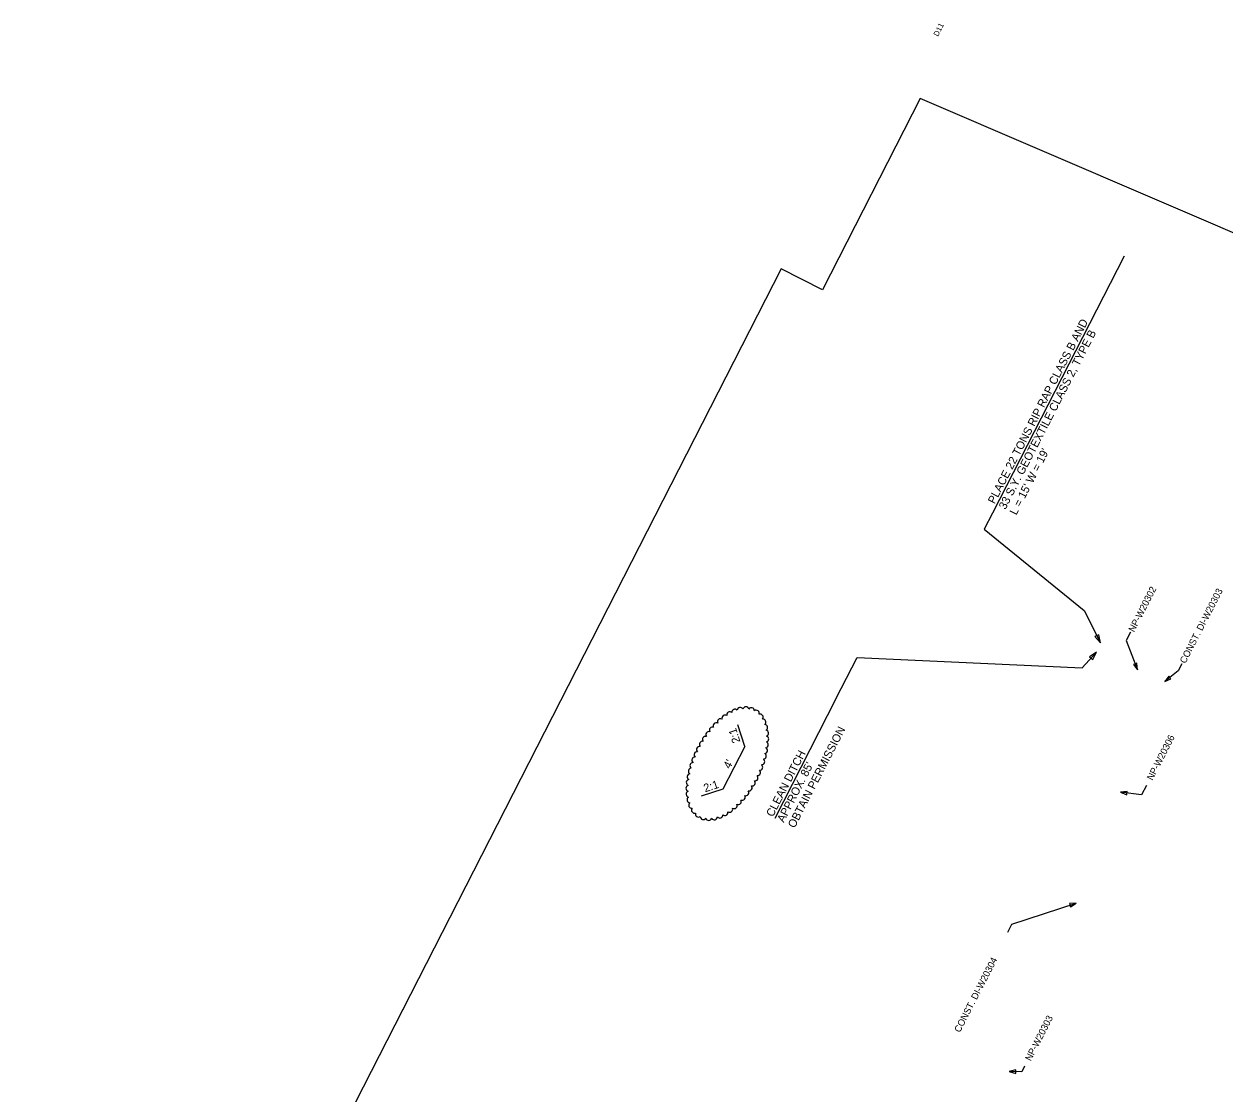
# Model space of a CAD drawing. Extents: x 1614575 to 1616117, y 1096819 to 1098677.
# Drawn here: x 1614575 to 1615461, y 1097888 to 1098677 of the extents above; entities that cross this region are included whole.
import ezdxf

# ---------------------------------------------------------------- set-up
doc = ezdxf.new("R2010")
doc.units = 0
for name, color, linetype in [('Level 19', 7, 'Continuous'), ('Level 2', 7, 'Continuous'), ('Level 20', 7, 'Continuous'), ('Level 8', 7, 'Continuous')]:
    doc.layers.add(name, color=color, linetype=linetype)

msp = doc.modelspace()

# ---------------------------------------------------------------- linework, layer by layer
at = {"layer": 'Level 19'}
msp.add_lwpolyline([(1614788.78, 1097308.44), (1614938.71, 1097183.17), (1614915.33, 1097153.87), (1614985.17, 1097098.15), (1614971.19, 1097080.18), (1615113.55, 1096967.95), (1615306.49, 1096819.15), (1616070.13, 1098243.47), (1615778.49, 1098389.73), (1615502.74, 1098507.9), (1615236.09, 1098622.18), (1615164.05, 1098481.19), (1615133.61, 1098496.74), (1614575.12, 1097403.7), (1614683.85, 1097348.14)], close=True, dxfattribs=at)
msp.add_lwpolyline([(1614788.78, 1097308.44), (1614938.71, 1097183.17), (1614915.33, 1097153.87), (1614985.17, 1097098.15), (1614971.19, 1097080.18), (1615113.55, 1096967.95), (1615306.49, 1096819.15), (1616070.13, 1098243.47), (1615778.49, 1098389.73), (1615502.74, 1098507.9), (1615236.09, 1098622.18), (1615164.05, 1098481.19), (1615133.61, 1098496.74), (1614575.12, 1097403.7), (1614683.85, 1097348.14)], close=True, dxfattribs=at)
msp.add_lwpolyline([(1614788.78, 1097308.44), (1614938.71, 1097183.17), (1614915.33, 1097153.87), (1614985.17, 1097098.15), (1614971.19, 1097080.18), (1615113.55, 1096967.95), (1615306.49, 1096819.15), (1616070.13, 1098243.47), (1615778.49, 1098389.73), (1615502.74, 1098507.9), (1615236.09, 1098622.18), (1615164.05, 1098481.19), (1615133.61, 1098496.74), (1614575.12, 1097403.7), (1614683.85, 1097348.14)], close=True, dxfattribs=at)
msp.add_lwpolyline([(1614788.78, 1097308.44), (1614938.71, 1097183.17), (1614915.33, 1097153.87), (1614985.17, 1097098.15), (1614971.19, 1097080.18), (1615113.55, 1096967.95), (1615306.49, 1096819.15), (1616070.13, 1098243.47), (1615778.49, 1098389.73), (1615502.74, 1098507.9), (1615236.09, 1098622.18), (1615164.05, 1098481.19), (1615133.61, 1098496.74), (1614575.12, 1097403.7), (1614683.85, 1097348.14)], close=True, dxfattribs=at)
msp.add_lwpolyline([(1614788.78, 1097308.44), (1614938.71, 1097183.17), (1614915.33, 1097153.87), (1614985.17, 1097098.15), (1614971.19, 1097080.18), (1615113.55, 1096967.95), (1615306.49, 1096819.15), (1616070.13, 1098243.47), (1615778.49, 1098389.73), (1615502.74, 1098507.9), (1615236.09, 1098622.18), (1615164.05, 1098481.19), (1615133.61, 1098496.74), (1614575.12, 1097403.7), (1614683.85, 1097348.14)], close=True, dxfattribs=at)
at = {"layer": 'Level 2'}
for p, q in [((1615106.71, 1098144.45), (1615101.61, 1098160.27)), ((1615106.71, 1098144.45), (1615090.51, 1098112.82)), ((1615090.51, 1098112.82), (1615074.69, 1098107.72))]:
    msp.add_line(p, q, dxfattribs=at)
for centre, start, end in [((1615095.69, 1098167.7), 48.24258, 193.24258), ((1615099.46, 1098169.61), 40.62705, 185.62705), ((1615103.45, 1098170.92), 30.63786, 175.63786), ((1615107.56, 1098171.38), 17.23139, 162.23139), ((1615111.58, 1098170.75), 359.95632, 144.95632), ((1615115.18, 1098168.91), 340.77376, 125.77376), ((1615118.04, 1098166.01), 323.49869, 108.49869), ((1615085.78, 1098159.67), 63.6026, 208.6026), ((1615088.86, 1098162.63), 59.29942, 204.29942), ((1615092.16, 1098165.33), 54.29127, 199.29127), ((1615120.06, 1098162.4), 310.09222, 95.09222), ((1615121.33, 1098158.41), 300.10304, 85.10304), ((1615077.81, 1098149.61), 74.17362, 219.17362), ((1615080.26, 1098153.12), 70.90872, 215.90872), ((1615082.92, 1098156.48), 67.4217, 212.4217), ((1615121.97, 1098154.23), 292.4875, 77.4875), ((1615122.12, 1098149.98), 286.43881, 71.43881), ((1615073.49, 1098142.2), 80.36514, 225.36514), ((1615075.55, 1098145.96), 77.30189, 222.30189), ((1615121.24, 1098141.49), 277.12748, 62.12748), ((1615121.85, 1098145.72), 281.43066, 66.43066), ((1615068.58, 1098130.32), 89.82176, 234.82176), ((1615070, 1098134.37), 86.55694, 231.55694), ((1615071.64, 1098138.33), 83.42851, 228.42851), ((1615119.16, 1098133.19), 269.82137, 54.82137), ((1615120.33, 1098137.31), 273.30838, 58.30838), ((1615066.49, 1098122.02), 97.12722, 242.12722), ((1615067.4, 1098126.2), 93.30846, 238.30846), ((1615116.1, 1098125.18), 263.42819, 48.42819), ((1615117.74, 1098129.14), 266.55646, 51.55646), ((1615065.61, 1098113.54), 106.43623, 251.43623), ((1615065.88, 1098117.79), 101.42962, 246.42962), ((1615109.93, 1098113.9), 254.17314, 39.17314), ((1615112.19, 1098117.55), 257.30158, 42.30158), ((1615114.24, 1098121.31), 260.36494, 45.36494), ((1615065.76, 1098109.29), 112.48287, 257.48287), ((1615066.41, 1098105.11), 120.09628, 265.09628), ((1615104.81, 1098107.03), 247.42162, 32.42162), ((1615107.47, 1098110.39), 250.90832, 35.90832), ((1615067.67, 1098101.12), 130.08625, 275.08625), ((1615069.7, 1098097.51), 143.49197, 288.49197), ((1615095.58, 1098098.18), 234.29385, 19.29385), ((1615098.88, 1098100.88), 239.30046, 24.30046), ((1615101.95, 1098103.85), 243.60287, 28.60287), ((1615072.56, 1098094.61), 160.76839, 305.76839), ((1615076.15, 1098092.77), 179.96169, 324.96169), ((1615080.18, 1098092.14), 197.23811, 342.23811), ((1615084.29, 1098092.6), 210.64384, 355.64384), ((1615088.27, 1098093.9), 220.63381, 5.63381), ((1615092.04, 1098095.82), 228.24721, 13.24721)]:
    msp.add_arc(centre, 2.27, start, end, dxfattribs=at)
at = {"layer": 'Level 8'}
for p, q in [((1615386.62, 1098506.07), (1615289.42, 1098316.4)), ((1615174, 1098179.43), (1615128.84, 1098091.3))]:
    msp.add_line(p, q, dxfattribs=at)
for points in [[(1615289.42, 1098316.4), (1615283.39, 1098304.64), (1615357.03, 1098244.58), (1615369.06, 1098220.96)], [(1615391.22, 1098228.61), (1615388.07, 1098222.46), (1615396.37, 1098200.91)], [(1615174, 1098179.43), (1615189.72, 1098210.09), (1615355.6, 1098202.34), (1615366.17, 1098213.85)], [(1615429.02, 1098205.39), (1615426.38, 1098200.23), (1615416.48, 1098192.37)], [(1615402.95, 1098115.66), (1615399.36, 1098108.65), (1615383.87, 1098110.61)], [(1615300.74, 1098007.48), (1615303.77, 1098013.39), (1615351.25, 1098028.85)], [(1615313.18, 1097908.71), (1615311.02, 1097904.49), (1615301.8, 1097904.82)]]:
    msp.add_lwpolyline(points, dxfattribs=at)
for points in [[(1615365.05, 1098225.42), (1615369.06, 1098220.96), (1615367.82, 1098226.83)], [(1615363.4, 1098208.53), (1615366.17, 1098213.85), (1615361.11, 1098210.63)], [(1615393.42, 1098204.95), (1615396.37, 1098200.91), (1615395.84, 1098205.88)], [(1615419.46, 1098196.39), (1615416.48, 1098192.37), (1615421.07, 1098194.36)], [(1615388.82, 1098111.29), (1615383.87, 1098110.61), (1615388.5, 1098108.72)], [(1615347.06, 1098026.12), (1615351.25, 1098028.85), (1615346.26, 1098028.58)], [(1615306.67, 1097905.94), (1615301.8, 1097904.82), (1615306.58, 1097903.36)]]:
    msp.add_lwpolyline(points, close=True, dxfattribs=at)

# ---------------------------------------------------------------- texts
at = {"layer": 'Level 2'}
for s, rotation, p in [('2:1', 107.86504, (1615103.61, 1098147.94)), ("4'", 62.86504, (1615095.88, 1098127.45)), ('2:1', 17.86504, (1615077.5, 1098110.59))]:
    msp.add_text(s, height=6, rotation=rotation, dxfattribs=at).set_placement(p)
at = {"layer": 'Level 20'}
msp.add_text('D11', height=4, rotation=62.86504, dxfattribs=at).set_placement((1615249.24, 1098667.67))
at = {"layer": 'Level 8'}
for s, height, p in [('PLACE 22 TONS RIP RAP CLASS B AND', 6, (1615291.03, 1098322.83)), ('33 S.Y. GEOTEXTILE CLASS 2, TYPE B', 6, (1615299.04, 1098318.73)), ("L = 15' W = 19'", 6, (1615307.04, 1098314.62)), ('NP-W20302', 5, (1615393.9, 1098228.36)), ('CONST. DI-W20303', 5, (1615431.71, 1098205.14)), ('OBTAIN PERMISSION', 6, (1615143.52, 1098083.78)), ('NP-W20306', 5, (1615407.46, 1098118.97)), ('CLEAN DITCH ', 6, (1615127.5, 1098091.99)), ("APPROX. 85'", 6, (1615135.51, 1098087.88)), ('CONST. DI-W20304', 5, (1615265.42, 1097933.08)), ('NP-W20303', 5, (1615317.68, 1097912.02))]:
    msp.add_text(s, height=height, rotation=62.86504, dxfattribs=at).set_placement(p)

doc.saveas('drawing.dxf')
